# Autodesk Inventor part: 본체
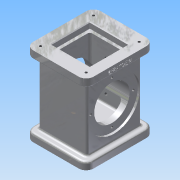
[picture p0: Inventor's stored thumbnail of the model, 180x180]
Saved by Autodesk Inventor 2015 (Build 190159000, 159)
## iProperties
Created: 2017-08
Part Number: 본체
Material: 알루미늄 6061
Document SubType Name: Modeling
Designer: Administrator
Density: 2.7 g/cm^3
Appearance: 알루미늄 - 평지
Mass: 1004.01 g
Surface Area: 664.104 cm^2
Volume: 371.855 cm^3
Author: Administrator
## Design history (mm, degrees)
sketch "스케치1"
  geometry: L1 (41, -46)-(-41, -46); L2 (-41, -46)-(-41, 46); L3 (-41, 46)-(41, 46); L4 (41, 46)-(41, -46); L5 (41, -46)-(-41, 46); L6 (-41, -46)-(41, 46); 1 further point
  constraints: 12 end point, 2 midpoint, 2 parallel, 1 horizontal, 1 perpendicular
  dimensions: "d0" = 82 distance between parallel lines of L2 L4; "d2" = 92 distance between parallel lines of L3 L1
extrude "돌출1" new body sketch "스케치1" distance "d3" = 10; taper "d4" = 0 deg
sketch "스케치2"
  geometry: L1 (-33, 37)-(33, 37); L2 (33, 37)-(33, -37); L3 (33, -37)-(-33, -37); L4 (-33, -37)-(-33, 37); L5 (-33, 37)-(33, -37); L6 (33, 37)-(-33, -37); 1 further point
  constraints: 12 end point, 2 midpoint, 2 parallel, 1 horizontal, 1 perpendicular
  dimensions: "d5" = 66 distance between parallel lines of L2 L4; "d6" = 74 distance between parallel lines of L3 L1
extrude "돌출2" join sketch "스케치2" distance "d7" = 88; taper "d8" = 0 deg
sketch "스케치6"
  geometry: L1 (-21, 21)-(21, 21); L2 (21, 21)-(21, -21); L3 (21, -21)-(-21, -21); L4 (-21, -21)-(-21, 21); L5 (-21, 21)-(21, -21); L6 (21, 21)-(-21, -21); 1 further point
  constraints: 12 end point, 2 midpoint, 2 parallel, 1 horizontal, 1 perpendicular
  dimensions: "d21" = 42 distance between parallel lines of L2 L4; "d22" = 42 distance between parallel lines of L3 L1
extrude "돌출6" cut sketch "스케치6" distance "d23" = 16; taper "d24" = 0 deg
sketch "스케치7"
  geometry: C1 r 35 at (37, 44); 1 further point
  constraints: 1 centre point, 1 vertical alignment
  dimensions: "d28" = 70 diameter of C1; "d29" = 54 distance of point (37, -10) C1.centre
extrude "돌출7" cut sketch "스케치7" distance "d30" = 3; taper "d31" = 0 deg
sketch "스케치8"
  geometry: C1 r 35 at (0, 0) reference; C2 r 24 at (0, 0); 1 further point
  constraints: 1 centre point, 1 coincident
  dimensions: "d32" = 48 diameter of C2
extrude "돌출8" cut sketch "스케치8" stored distance "d33" = 3; taper "d34" = 0 deg
sketch "스케치9"
  geometry: C1 r 24 at (0, 0) reference; 2 further points
  constraints: 1 vertical alignment
  dimensions: "d35" = 29 distance of C1.centre point (0, 29)
hole "구멍1" sketch "스케치9" at (0, 29) diameter "d36" = 3.242; stored, may be unused: countersink angle "d40" = 90 deg, drill point angle "d42" = 118 deg; dims "d37" = 4, "d38" = 4, "d39" = 2, "d41" = 6
fillet "모깎기2" dims "d60" = 10
sketch "스케치14"
  geometry: L1 (-41, -46)-(41, -46); L2 (41, -46)-(41, 46); L3 (41, 46)-(-41, 46); L4 (-41, 46)-(-41, -46); L5 (-41, -46)-(41, 46); L6 (41, -46)-(-41, 46); 1 further point
  constraints: 12 end point, 2 midpoint, 2 parallel, 1 horizontal, 1 perpendicular
  dimensions: "d77" = 92 distance between parallel lines of L3 L1; "d78" = 82 distance between parallel lines of L2 L4
extrude "돌출9" join sketch "스케치14" distance "d79" = 10; taper "d80" = 0 deg
sketch "스케치15"
  geometry: L1 (-26, 26)-(26, 26); L2 (26, 26)-(26, -26); L3 (26, -26)-(-26, -26); L4 (-26, -26)-(-26, 26); L5 (-26, 26)-(26, -26); L6 (26, 26)-(-26, -26); 1 further point
  constraints: 12 end point, 2 midpoint, 2 parallel, 1 horizontal, 1 perpendicular
  dimensions: "d81" = 52 distance between parallel lines of L4 L2; "d82" = 52 distance between parallel lines of L3 L1
extrude "돌출10" cut sketch "스케치15" distance "d83" = 8; taper "d84" = 0 deg
sketch "스케치16"
  geometry: L1 (-22, 22)-(22, 22); L2 (22, 22)-(22, -22); L3 (22, -22)-(-22, -22); L4 (-22, -22)-(-22, 22); L5 (-22, 22)-(22, -22); L6 (22, 22)-(-22, -22); 1 further point
  constraints: 12 end point, 2 midpoint, 2 parallel, 1 horizontal, 1 perpendicular
  dimensions: "d85" = 44 distance between parallel lines of L4 L2; "d86" = 44 distance between parallel lines of L3 L1
extrude "돌출11" cut sketch "스케치16" distance "d87" = 74; taper "d88" = 0 deg
fillet "모깎기3" dims "d89" = 10
sketch "스케치17"
  geometry: A1 r 10 centre (31, 36) between (41, 36) and (31, 46) reference; 2 further points
  constraints: 1 coincident
hole "구멍4" sketch "스케치17" at (31, 36) diameter "d90" = 3.242; stored, may be unused: countersink angle "d94" = 90 deg, drill point angle "d96" = 118 deg; dims "d91" = 4, "d92" = 4, "d93" = 2, "d95" = 6
node "작업 평면2"
sketch "스케치18"
  geometry: L1 (0, 0)-(72, 0) reference; L2 (0, 10)-(-10, 10) reference; L3 (-10, 10)-(-10, 0) reference; L4 (-10, 0)-(0, 0) reference; L5 (0, 0)-(0, 10) reference; 2 further points
  constraints: 1 other
  dimensions: "d103" = 46 distance from line of L3 point (36, 4); "d104" = 4 distance from line of L1 point (36, 4)
feature "엠보싱2" sketch "스케치18" dims "d21" = 42, "d22" = 42, "d105" = 0.5, "d106" = 0
fillet "모깎기4" dims "d107" = 3
fillet "모깎기5" dims "d108" = 3
fillet "모깎기6" dims "d109" = 3
fillet "모깎기7" dims "d110" = 3
fillet "모깎기9" dims "d112" = 3
fillet "모깎기10" dims "d113" = 3
fillet "모깎기11" dims "d114" = 3
sketch "스케치19"
  geometry: L1 (61, -95)-(-1, -95) reference; 4 further points
  constraints: 2 vertical alignment, 1 midpoint
  dimensions: "d115" = 38 distance from line of L1 point (30, -57); "d116" = 42 distance of point (30, -57) point (30, -15)
hole "구멍5" sketch "스케치19" at (30, -57), (30, -15) diameter "d117" = 4.134; stored, may be unused: countersink angle "d121" = 90 deg, drill point angle "d123" = 0 deg; dims "d118" = 10, "d119" = 4, "d120" = 2, "d122" = 50
chamfer "모따기1" distance "d124" = 1; stored, may be unused: second distance "d125" = 2, angle "d126" = 45 deg
fillet "모깎기12" dims "d127" = 1
fillet "모깎기13" dims "d128" = 3
fillet "모깎기14" dims "d129" = 3
node "솔리드1"
mirror "대칭1"
pattern_circular "원형 패턴1" dims angle "d44" = 360 deg
mirror "대칭2"
pattern_linear "직사각형 패턴2" dims "d99" = 72, "d102" = 62
mirror "대칭4"
node "투영된 루프3"
